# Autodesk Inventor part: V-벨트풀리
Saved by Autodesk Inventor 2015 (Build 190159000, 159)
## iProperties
Created: 2026-07
Part Number: V-벨트풀리
Material: 일반
Document SubType Name: Modeling
Designer: USER
Density: 1 g/cm^3
Appearance: 기본값
Author: USER
Author: jhkim
Creation Date: 2026-07-01
Sending System: Autodesk Inventor 2027
Preprocessor: ST-DEVELOPER v20.1
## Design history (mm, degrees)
node "V-벨트풀리1"
body "Solid1"
node "기준1"
